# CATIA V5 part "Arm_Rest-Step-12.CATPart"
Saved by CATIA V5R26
Part number: Arm_Rest
Bounding box of the stored display mesh (mm): x 766.594 to 1406.039, y -781.99 to -669.51, z 394.789 to 524.009
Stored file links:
  D:\LinkedIn Learning\NURBS\CATIA\Class Parts\Arm_Rest-Step-13.CATPart
  D:\LinkedIn Learning\NURBS\Arm_Rest.CATPart
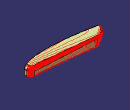
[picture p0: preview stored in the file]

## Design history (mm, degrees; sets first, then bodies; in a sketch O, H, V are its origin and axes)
AxisSystem1: origin (0, 0, 0), X (1, 0, 0), Y (0, 1, 0), Z (0, 0, 1)
StDynAnalysisRootNodeFeature1 "CATStDynAnalysisRootNodeName"
Set1 "REF DATA"
  CLDGeom1 "TOP"
  CLDGeom2 "FRONT"
  CLDGeom3 "AFT_BLEND"
  CLDGeom4 "END_AFT"
  CLDGeom5 "FORWARD_BLEND"
  CLDGeom6 "BOTTOM"
  CLDGeom7 "END_FORWARD"
  CLDGeom8 "UPPER_BLENDS"
  CLDGeom9 "LOWER_BLENDS"
  DatumSurface1 "DOOR_TRIM_SURFACE"
Set2 "FORM"
  Set3 "SLABS"
    DatumSurface2 to DatumSurface6
  Set4 "CURVES"
    St3DCurveFeature1 "CATSt3DCurveFeatureName": Order 6, CreationType 1, ClosureMode false, ConstructionPoints ({point type Coord, X 863.1168, Y 0, Z 551.1449}; {point type Coord, X 868.9503, Y 0, Z 330.43}), SymmetryMode false
    St3DCurveFeature2 "CATSt3DCurveFeatureName": Order 6, CreationType 1, ClosureMode false, ConstructionPoints ({point type Coord, X 1369.3867, Y 0, Z 551.9965}; {point type Coord, X 1358.4038, Y 0, Z 335.6826}), SymmetryMode false
    Intersect1: ToIntersect1 DatumSurface4, ToIntersect2 DatumSurface5
    Intersect2: ToIntersect1 DatumSurface6, ToIntersect2 DatumSurface4
    CurvePar1: Offset Intersect2, Support DatumSurface6, Offset2 0, Offset1 30
    CurvePar2: Offset Intersect1, Support DatumSurface5, Offset2 50, Offset1 20
    Project1: ToProject St3DCurveFeature1, Support DatumSurface4, Direction edge [YZ plane of AxisSystem1 | XY plane of AxisSystem1]
    Project2: ToProject St3DCurveFeature2, Support DatumSurface4, Direction edge [YZ plane of AxisSystem1 | XY plane of AxisSystem1]
    Project3: ToProject St3DCurveFeature2, Support StTopoTypeFeature3, Direction edge [YZ plane of AxisSystem1 | XY plane of AxisSystem1]
    Project4: ToProject St3DCurveFeature1, Support StTopoTypeFeature3, Direction edge [YZ plane of AxisSystem1 | XY plane of AxisSystem1]
    Intersect3: ToIntersect1 edge of StTopoTypeFeature1, ToIntersect2 CurvePar2
    Intersect4: ToIntersect1 edge of StTopoTypeFeature2, ToIntersect2 CurvePar1
    Project5: ToProject Intersect4, Support edge of StTopoTypeFeature2
    Project6: ToProject Intersect3, Support edge of StTopoTypeFeature1
    Line1: type PtPt, FirstPoint Intersect3, SecondPoint Project6, Support StTopoTypeFeature1
    Line2: type PtPt, FirstPoint Intersect4, SecondPoint Project5, Support StTopoTypeFeature2
    Curve1: Elements (Intersect4; vertex of Project3), Support Blend2
    Curve2: Elements (Project5; vertex of Project3), Support DatumSurface2
    Curve3: Elements (vertex of Project4; Intersect3), Support Blend1
    Curve4: Elements (vertex of Project4; Project6), Support DatumSurface2
  Set5 "BLENDS"
    Blend1: StartLimit {blendlimit Curve Project1, Support DatumSurface4, TensionValues 1.1}, EndLimit {blendlimit Curve CurvePar2, Support DatumSurface5, TensionValues 1}
    Blend2: StartLimit {blendlimit Curve CurvePar1, Support DatumSurface6, TensionValues 0.9}, EndLimit {blendlimit Curve Project2, Support DatumSurface4, TensionValues 0.8}
    StTopoTypeFeature1 "CATStTopoTypeFeatureName": Children 15
    StTopoTypeFeature2 "CATStTopoTypeFeatureName": Children 35
    StTopoTypeFeature3 "CATStTopoTypeFeatureName": nls://CATStFeaturesStartUpsNLS/TopoVarRadiCke 35, nls://CATStFeaturesStartUpsNLS/TopoVarRadiCke 15
    Loft1: Sections (Line2; Project3), StartSectionTangent StTopoTypeFeature2, EndSectionTangent StTopoTypeFeature3, Guides ({loftguide GuideCurve Curve1, GuideTangent Blend2}; {loftguide GuideCurve Curve2, GuideTangent DatumSurface2})
    Loft2: Sections (Project4; Line1), StartSectionTangent StTopoTypeFeature3, EndSectionTangent StTopoTypeFeature1, Guides ({loftguide GuideCurve Curve3, GuideTangent Blend1}; {loftguide GuideCurve Curve4, GuideTangent DatumSurface2})
  Set6 "SPLITS"
    Split1: ToCut DatumSurface4, Cutting (Project1; edge of StTopoTypeFeature3; Project2)
    Split2: ToCut Blend2, Cutting Curve1
    Split3: ToCut DatumSurface6, Cutting (CurvePar1; edge of StTopoTypeFeature2)
    Split4: ToCut Blend1, Cutting Curve3
    Split5: ToCut DatumSurface5, Cutting (CurvePar2; edge of StTopoTypeFeature1)
    Split6: ToCut StTopoTypeFeature1, Cutting Line1
    Split7: ToCut StTopoTypeFeature3, Cutting (Project4; Project3)
    Split8: ToCut StTopoTypeFeature2, Cutting Line2
    Split9: ToCut DatumSurface2, Cutting (edge of StTopoTypeFeature3; edge of StTopoTypeFeature2; Curve2; edge of StTopoTypeFeature1; Curve4)
  Join1: Elements (Split9; Loft1; Loft2; Split6; Split7; Split8; Split2; Split4; Split5; Split1; Split3)
  StTopoTypeFeature4 "CATStTopoTypeFeatureName": Children 13
  Split10: ToCut StTopoTypeFeature4, Cutting DatumSurface1
Body1 (main body)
